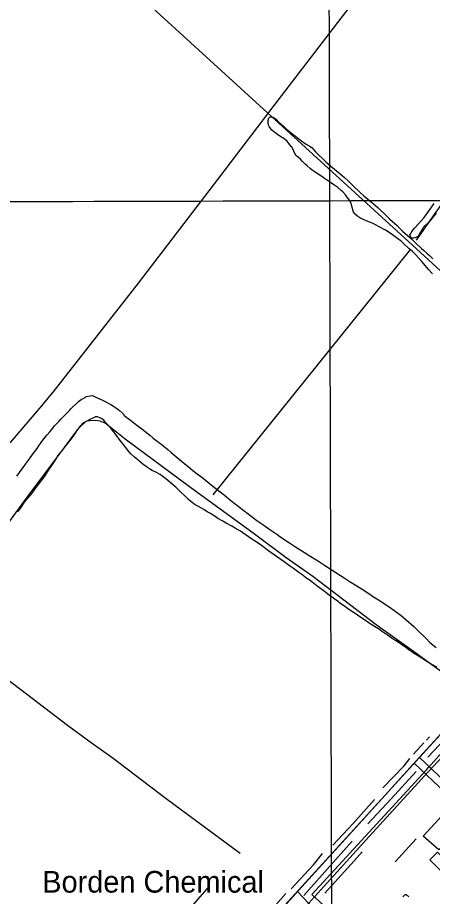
# Model space of a CAD drawing. Extents: x 3355677 to 3393573, y 612928 to 638357.
# Drawn here: x 3379651 to 3381245, y 621756 to 625128 of the extents above; entities that cross this region are included whole.
import ezdxf

# ---------------------------------------------------------------- set-up
doc = ezdxf.new("R2010")
doc.units = 0
for name, color, linetype in [('V-BLDG-IDEN', 7, 'Continuous'), ('V-BLDG-OTLN', 7, 'Continuous'), ('V-GRID-MAJR', 7, 'Continuous'), ('V-RAIL-TRAK', 7, 'Continuous'), ('V-ROAD-CNTR', 7, 'Continuous'), ('V-SITE-OTLN', 7, 'Continuous'), ('V-SITE-VEGE', 7, 'Continuous'), ('V-TOPO-SHOR', 7, 'Continuous')]:
    doc.layers.add(name, color=color, linetype=linetype)

msp = doc.modelspace()

# ---------------------------------------------------------------- linework, layer by layer
at = {"layer": 'V-BLDG-OTLN'}
for points in [[(3381209.288, 621987.415), (3381311.055, 622097.518), (3381369.585, 622043.42), (3381269.2290000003, 621934.845)], [(3381263.917434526, 621924.786123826), (3381309.888342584, 621879.4052145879), (3381281.234399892, 621850.3782726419), (3381235.263491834, 621895.75918188)]]:
    msp.add_lwpolyline(points, close=True, dxfattribs=at)
at = {"layer": 'V-GRID-MAJR'}
for points in [[(3380867.299, 618367.203), (3380850.557, 624425.373), (3380833.806, 630486.627), (3380817.056, 636547.903), (3380817.048, 636550.964)], [(3359794.3370000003, 624373.309), (3365058.395, 624385.176), (3370322.451, 624397.809), (3375586.505, 624411.208), (3380850.557, 624425.373), (3386114.607, 624440.303), (3391378.654, 624455.998), (3391378.6550000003, 624455.998)]]:
    msp.add_spline(points, degree=3, dxfattribs=at)
at = {"layer": 'V-RAIL-TRAK'}
msp.add_lwpolyline([(3380352.6180000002, 621270.75), (3380496.7460000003, 621429.9720000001), (3380576.2, 621518.388), (3380756.577, 621716.024), (3380791.531, 621754.129), (3380988.411, 621971.166), (3381228.473, 622233.525), (3381284.054, 622294.185), (3381306.678, 622314.102), (3381331.119, 622332.5480000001), (3381382.119, 622371.0380000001), (3381417.934, 622404.226), (3381617.665, 622615.6)], dxfattribs=at)
at = {"layer": 'V-ROAD-CNTR'}
for points in [[(3381890.5160000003, 626417.159), (3381710.773, 626181.361), (3381460.452, 625852.759), (3381172.455, 625486.251), (3380892.9390000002, 625126.385), (3380635.08, 624791.1460000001), (3380402.64, 624485.273), (3380114.671, 624109.317), (3379791.8510000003, 623697.356), (3379742.903, 623637.685), (3379622.393, 623497.4890000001), (3379412.3910000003, 623270.104)], [(3379694.12, 620644.703), (3382535.952, 623757.551), (3384147.191, 625535.174)], [(3380013.162, 620986.814), (3380148.012, 621136.819), (3380307.222, 621312.087), (3380410.13, 621425.376), (3380539.8310000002, 621568.355), (3380711.0500000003, 621757.099), (3380717.8310000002, 621764.574), (3381051.174, 622131.482), (3381182.666, 622275.468), (3381362.681, 622472.594), (3381699.823, 622844.278), (3382051.221, 623227.438), (3382358.918, 623567.588), (3382672.3200000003, 623912.5210000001), (3382981.928, 624250.768), (3383331.417, 624635.829), (3383600.1890000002, 624929.17), (3383887.949, 625245.439), (3384037.357, 625413.979), (3384075.974, 625457.542)], [(3381174.878, 622267.031), (3381294.137, 622154.61), (3381653.116, 621817.75), (3381716.602, 621758.354)], [(3381195.4560000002, 622288.861), (3381314.691, 622176.464), (3381673.628, 621839.642), (3381736.974, 621780.377)], [(3380726.767, 621774.258), (3380790.6, 621707.121), (3381148.342, 621385.496), (3381270.841, 621271.184)]]:
    msp.add_lwpolyline(points, dxfattribs=at)
at = {"layer": 'V-SITE-OTLN'}
for p, q in [((3381229.524301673, 622250.1162344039), (3381718.9743102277, 622801.2722410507)), ((3380781.434835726, 621763.3096493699), (3381220.6853120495, 622240.5132424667)), ((3381220.6853120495, 622240.5132424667), (3381229.524301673, 622250.1162344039)), ((3381114.8019789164, 621460.2037606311), (3380781.434835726, 621763.3096493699))]:
    msp.add_line(p, q, dxfattribs=at)
at = {"layer": 'V-SITE-VEGE'}
for points in [[(3380900.822, 624459.593), (3380893.5640000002, 624465.1410000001), (3380881.278, 624475.686), (3380870.114, 624483.4500000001), (3380852.811, 624495.095), (3380830.486, 624510.623), (3380820.438, 624517.834), (3380794.7660000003, 624534.466), (3380783.044, 624542.787), (3380775.2260000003, 624548.89), (3380763.498, 624559.439), (3380756.237, 624565.542), (3380744.506, 624577.203), (3380738.356, 624584.429), (3380729.423, 624592.197), (3380720.488, 624599.412), (3380704.792, 624632.227), (3380702.561, 624633.335), (3380698.648, 624638.334), (3380693.057, 624645.002), (3380685.227, 624655.005), (3380670.156, 624666.099), (3380664.575, 624669.425), (3380658.994, 624673.306), (3380650.065, 624678.85), (3380639.458, 624686.616), (3380634.435, 624690.501), (3380628.289, 624696.608), (3380624.375, 624701.609), (3380621.02, 624705.496), (3380617.666, 624709.9400000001), (3380616.541, 624713.281), (3380614.856, 624717.733), (3380613.7290000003, 624721.628), (3380613.16, 624725.5260000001), (3380613.154, 624728.313), (3380613.697, 624732.767), (3380615.356, 624736.6730000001), (3380615.343, 624740.5700000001), (3380616.453, 624742.245), (3380617.559, 624744.478), (3380619.2260000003, 624745.596), (3380622.012, 624746.161), (3380624.236, 624747.281), (3380628.1350000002, 624747.294), (3380632.594, 624746.194), (3380636.4990000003, 624743.976), (3380644.8710000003, 624738.432), (3380654.931, 624727.324), (3380664.43, 624717.882), (3380672.247, 624711.2220000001), (3380683.978, 624700.118), (3380695.146, 624691.24), (3380710.219, 624679.589), (3380714.129, 624676.259), (3380725.292, 624667.938), (3380732.554, 624661.2760000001), (3380757.671, 624644.085), (3380773.295, 624634.662), (3380782.2290000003, 624628.563), (3380795.643, 624613.006), (3380805.701, 624602.453), (3380824.131, 624586.356), (3380835.864, 624574.137), (3380854.8510000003, 624558.042), (3380868.255, 624546.387), (3380890.031, 624528.0700000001), (3380907.343, 624514.201), (3380924.098, 624499.209), (3380940.858, 624482.551), (3380965.998, 624458.118), (3380981.077, 624444.2390000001), (3381003.9760000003, 624424.257), (3381017.3740000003, 624414.273), (3381035.806, 624397.616), (3381045.855, 624389.291), (3381058.7090000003, 624375.963), (3381067.0870000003, 624368.188), (3381081.609, 624354.307), (3381091.663, 624345.427), (3381108.977, 624330.4400000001), (3381119.034, 624319.329), (3381130.2060000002, 624308.78), (3381158.133, 624283.801), (3381160.926, 624281.024), (3381173.214, 624269.921), (3381181.591, 624262.704), (3381202.261, 624242.159), (3381210.08, 624235.4990000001), (3381224.6010000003, 624222.731), (3381232.9790000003, 624214.957), (3381246.387, 624202.186)], [(3381244.89, 624144.254), (3381229.244, 624161.476), (3381218.061, 624174.808), (3381203.5270000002, 624192.589), (3381194.024, 624203.699), (3381178.936, 624219.809), (3381168.324, 624229.799), (3381154.356, 624242.5700000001), (3381132.021, 624261.998), (3381124.198, 624269.772), (3381110.242, 624279.756), (3381106.335, 624283.086), (3381086.236, 624298.622), (3381065.029, 624311.928), (3381040.481, 624324.662), (3381026.532, 624332.4180000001), (3381017.048, 624337.403), (3381002.548, 624343.486), (3380994.182, 624347.358), (3380982.47, 624352.337), (3380974.1040000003, 624356.212), (3380966.293, 624360.089), (3380958.482, 624364.518), (3380947.316, 624373.952), (3380941.721, 624381.738), (3380937.223, 624395.089), (3380931.583, 624417.908), (3380925.988, 624426.804), (3380916.477, 624440.145), (3380910.325, 624448.48), (3380900.822, 624459.593)], [(3381258.667, 624377.1240000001), (3381230.364, 624343.6190000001), (3381219.257, 624331.888), (3381213.148, 624326.299), (3381209.261, 624322.387), (3381205.933, 624317.365), (3381198.732, 624305.09), (3381192.083, 624293.373), (3381188.198, 624288.3470000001), (3381178.7460000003, 624282.75), (3381173.735, 624282.177), (3381165.383, 624281.0380000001), (3381161.473, 624284.368), (3381158.671, 624289.928), (3381158.102, 624293.824), (3381161.424, 624299.963), (3381165.862, 624306.66), (3381175.846, 624320.058), (3381190.8370000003, 624336.256), (3381212.487, 624360.83), (3381226.356, 624379.254), (3381235.7830000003, 624393.209), (3381251.315, 624414.4180000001)], [(3379878.258, 623647.938), (3379884.828, 623654.549), (3379895.789, 623662.27), (3379903.465, 623666.687), (3379910.592, 623670.554), (3379912.781, 623673.304), (3379916.072, 623674.414), (3379929.794, 623677.201), (3379939.128, 623677.228), (3379944.625, 623675.598), (3379953.9760000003, 623670.685), (3379977.623, 623660.322), (3379987.525, 623654.862), (3380001.279, 623646.664), (3380009.528, 623642.844), (3380019.981, 623636.833), (3380027.137, 623631.363), (3380035.9420000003, 623625.899), (3380042.548, 623619.878), (3380054.66, 623610.578), (3380059.072, 623604.551), (3380059.631, 623601.258), (3380064.032, 623599.074), (3380075.593, 623589.772), (3380085.501, 623582.666), (3380102.563, 623569.534), (3380109.17, 623564.062), (3380128.433, 623550.3910000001), (3380159.264, 623525.221), (3380171.927, 623514.277), (3380192.845, 623498.4130000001), (3380207.154, 623488.022), (3380228.075, 623471.06), (3380241.841, 623459.02), (3380264.414, 623440.416), (3380280.934, 623426.186), (3380306.81, 623404.846), (3380323.878, 623390.6190000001), (3380341.4930000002, 623376.944), (3380359.106, 623363.817), (3380400.944, 623330.4400000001), (3380445.535, 623295.43), (3380470.31, 623275.183), (3380487.376, 623261.507), (3380553.432, 623210.632), (3380570.492, 623198.602), (3380596.907, 623180.559), (3380616.722, 623166.338), (3380647.54, 623145.563), (3380659.097, 623136.812), (3380695.967, 623112.76), (3380718.532, 623097.452), (3380777.4080000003, 623059.736), (3380810.421, 623038.9670000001), (3380830.778, 623026.3960000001), (3380859.393, 623007.811), (3380906.163, 622977.746), (3380925.427, 622965.1730000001), (3380954.035, 622947.687), (3380974.392, 622935.117), (3381000.806, 622918.172), (3381017.867, 622905.593), (3381043.727, 622889.743), (3381053.083, 622883.182), (3381078.947, 622866.236), (3381096.007, 622854.204), (3381124.077, 622833.97), (3381143.348, 622817.553), (3381173.083, 622791.282), (3381191.808, 622773.765), (3381218.803, 622746.388), (3381235.326, 622729.963), (3381258.45, 622710.81)], [(3379648.9960000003, 623367.71), (3379679.071, 623410.638), (3379688.369, 623423.297), (3379697.669, 623435.406), (3379708.6040000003, 623451.915), (3379726.108, 623475.033), (3379732.67, 623484.39), (3379742.514, 623497.6), (3379748.531, 623505.856), (3379757.829, 623517.965), (3379764.393, 623526.774), (3379774.793, 623538.89), (3379783.003, 623547.698), (3379793.399, 623560.91), (3379797.2290000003, 623565.3150000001), (3379809.273, 623578.533), (3379817.481, 623587.343), (3379839.383, 623609.378), (3379850.335, 623619.845), (3379856.356, 623626.454), (3379863.469, 623634.714), (3379878.258, 623647.938)], [(3381197.606, 622673.282), (3381187.149, 622680.389), (3381172.293, 622689.68), (3381164.037, 622695.697), (3381155.233, 622701.162), (3381143.123, 622710.462), (3381134.3170000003, 622715.928), (3381123.313, 622723.581), (3381116.7060000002, 622729.053), (3381103.498, 622737.8), (3381094.147, 622742.715), (3381079.289, 622753.105), (3381053.4250000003, 622770.601), (3381041.864, 622779.352), (3381028.656, 622788.099), (3381006.1, 622801.761), (3380984.086, 622817.0700000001), (3380970.329, 622825.817), (3380957.122, 622835.113), (3380944.465, 622843.311), (3380927.9560000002, 622854.245), (3380918.603, 622860.258), (3380908.144, 622868.465), (3380888.3310000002, 622882.135), (3380883.926, 622885.965), (3380847.6010000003, 622912.216), (3380829.986, 622925.344), (3380805.217, 622943.942), (3380789.8000000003, 622956.527), (3380774.94, 622967.465), (3380761.734, 622975.661), (3380743.566, 622990.435), (3380731.461, 622998.638), (3380710.542, 623014.4990000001), (3380695.684, 623024.34), (3380674.77, 623039.655), (3380658.808, 623051.689), (3380633.4930000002, 623068.636), (3380614.7800000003, 623082.309), (3380588.359, 623102), (3380571.848, 623114.032), (3380547.636, 623129.337), (3380507.465, 623156.674), (3380487.106, 623169.242), (3380473.9020000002, 623176.8910000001), (3380452.998, 623188.36), (3380439.248, 623195.459), (3380421.092, 623205.84), (3380410.0870000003, 623212.944), (3380391.931, 623224.4230000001), (3380379.825, 623231.5260000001), (3380367.169, 623240.275), (3380346.8140000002, 623251.7440000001), (3380333.612, 623258.844), (3380317.099, 623270.876), (3380306.6380000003, 623280.182), (3380295.62, 623291.133), (3380275.793, 623309.743), (3380259.823, 623324.524), (3380235.595, 623345.321), (3380220.728, 623357.908), (3380198.71, 623374.863), (3380184.407, 623382.511), (3380167.911, 623390.148), (3380162.406, 623393.426), (3380153.603, 623399.441), (3380145.899, 623404.361), (3380132.687, 623414.754), (3380105.7090000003, 623437.1900000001), (3380100.2060000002, 623441.018), (3380085.8880000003, 623453.607), (3380078.171, 623462.917), (3380066.041, 623479.356), (3380056.667, 623491.411), (3380041.7800000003, 623510.0380000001), (3380032.958, 623522.643), (3380019.725, 623540.178), (3380009.803, 623552.228), (3379996.579, 623567.017), (3379989.415, 623574.685), (3379982.251, 623582.899), (3379978.397, 623586.182), (3379971.792, 623590.008), (3379967.395, 623592.191), (3379960.798, 623594.368), (3379958.0500000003, 623595.456), (3379949.811, 623595.433), (3379946.522, 623593.774), (3379942.682, 623592.115), (3379931.166, 623586.59), (3379912.523, 623577.198), (3379906.498, 623571.686), (3379888.426, 623554.608), (3379882.403, 623548.5480000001), (3379880.762, 623546.3470000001), (3379877.48, 623542.492), (3379873.656, 623535.892), (3379870.9220000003, 623531.488), (3379865.452, 623523.784), (3379863.811, 623521.033), (3379850.686, 623503.969)], [(3379850.686, 623503.969), (3379835.367, 623484.7000000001), (3379823.328, 623469.835), (3379806.373, 623447.268), (3379796.532, 623432.41), (3379781.224, 623409.8470000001), (3379770.8340000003, 623394.987), (3379757.1720000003, 623372.428), (3379747.876, 623359.221), (3379734.748, 623341.608), (3379724.355, 623328.3960000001), (3379710.1350000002, 623308.582), (3379699.193, 623295.368), (3379682.227, 623275.5480000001), (3379676.757, 623268.392), (3379661.995, 623246.376), (3379651.059, 623230.969)], [(3381261.424, 622635.58), (3381239.971, 622647.049), (3381226.767, 622654.699), (3381209.159, 622666.178), (3381197.606, 622673.282)]]:
    msp.add_lwpolyline(points, dxfattribs=at)
at = {"layer": 'V-TOPO-SHOR'}
for p, q in [((3378706.644148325, 626501.2733637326), (3381167.927492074, 624254.681401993)), ((3381160.2599427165, 624239.3463032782), (3380401.1725563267, 623296.2377323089)), ((3381167.927492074, 624254.681401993), (3382065.0307668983, 623434.2536207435)), ((3381221.299, 622355.537), (3381233.544, 622367.858)), ((3381172.3340000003, 622301.535), (3381211.8850000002, 622345.117)), ((3381101.02, 621888.3640000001), (3381182.127, 621976.606)), ((3380385.837457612, 621793.3980582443), (3379964.122242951, 621310.3424487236))]:
    msp.add_line(p, q, dxfattribs=at)
for points in [[(3381182.9790000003, 624274.394), (3381239.4220000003, 624354.872), (3381289.285, 624424.939), (3381335.3910000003, 624487.435), (3381395.66, 624552.807), (3381450.233, 624627.613), (3381563.166, 624773.453), (3381593.2800000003, 624813.225), (3381654.441, 624895.608), (3381765.498, 625037.6630000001), (3381815.404, 625093.557), (3381833.2600000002, 625124.789)], [(3381389.907, 622539.501), (3381280.075, 622617.585), (3381163.607, 622702.265), (3381028.2120000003, 622798.224), (3380785.784, 622983.616), (3380683.529, 623055.109), (3380556.639, 623150.1510000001), (3380311.398, 623327.974), (3380064.253, 623510.519), (3379987.541, 623571.699), (3379968.622, 623579.199), (3379948.772, 623581.974), (3379928.936, 623580.968), (3379919.49, 623579.995), (3379901.5640000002, 623571.437), (3379880.8510000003, 623547.756), (3379830.044, 623477.685), (3379687.949, 623289.243), (3379526.116, 623067.67)], [(3381226.966, 622289.385), (3381316.435, 622384.133), (3381454.861, 622535.72), (3381575.386, 622671.191), (3381694.9790000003, 622801.933)], [(3380506.218, 621919.841), (3380368.916, 622021.463), (3380222.146, 622129.671), (3380013.809, 622288.711), (3379933.3310000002, 622345.156), (3379843.372, 622411.963), (3379663.447, 622548.416), (3379534.663, 622645.339), (3379468.379, 622694.268)], [(3381054.625, 622172.687), (3381136.569, 622256.078), (3381158.211, 622285.432)], [(3380997.2090000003, 622033.593), (3381085.73, 622130.23), (3381182.727, 622234.451)], [(3380862.553, 621951.968), (3380939.775, 622035.344), (3381021.693, 622127.238)], [(3380750.505, 621758.856), (3380840.9, 621860.2220000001), (3380936.9450000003, 621967.275)], [(3380702.443, 621785.2000000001), (3380788.145, 621876.16), (3380822.969, 621919.727)], [(3380831.491, 621767.5210000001), (3380932.396, 621879.479), (3380974.8310000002, 621926.917)], [(3380518.813, 621585.292), (3380604.503, 621680.033), (3380681.715, 621766.241)], [(3381131.5270000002, 621754.189), (3381134.147, 621757.056), (3381136.381, 621759.383), (3381138.54, 621761.553), (3381141.083, 621763.493), (3381144.409, 621762.962), (3381146.6580000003, 621760.806), (3381148.751, 621758.492), (3381151.309, 621756.182), (3381153.865, 621754.103)]]:
    msp.add_lwpolyline(points, dxfattribs=at)

# ---------------------------------------------------------------- texts
at = {"layer": 'V-BLDG-IDEN'}
msp.add_text('Borden Chemical', height=82.99983200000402, rotation=359.9880981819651, dxfattribs=at).set_placement((3379746.1284701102, 621770.22943294))

doc.saveas('drawing.dxf')
